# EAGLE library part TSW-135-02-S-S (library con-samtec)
THROUGH-HOLE .025" SQ POST HEADER Source: Samtec TSW.pdf
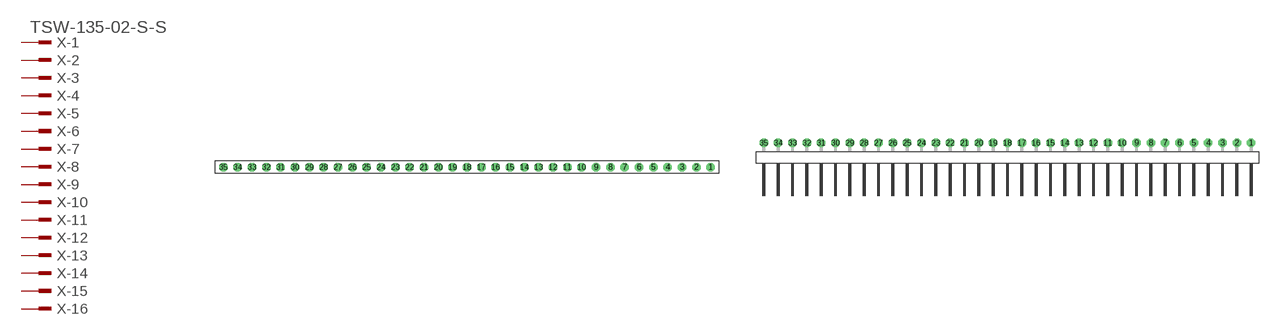
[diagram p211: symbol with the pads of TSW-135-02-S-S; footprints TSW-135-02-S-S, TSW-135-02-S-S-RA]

Designator prefix X; gates -1=MPINV -2=MPIN -3=MPIN -4=MPIN -5=MPIN -6=MPIN -7=MPIN -8=MPIN -9=MPIN -10=MPIN -11=MPIN -12=MPIN -13=MPIN -14=MPIN -15=MPIN -16=MPIN -17=MPIN -18=MPIN -19=MPIN -20=MPIN -21=MPIN -22=MPIN -23=MPIN -24=MPIN -25=MPIN -26=MPIN -27=MPIN -28=MPIN -29=MPIN -30=MPIN -31=MPIN -32=MPIN -33=MPIN -34=MPIN -35=MPIN

## TSW-135-02-S-S (OC_FARNELL: unknown; OC_NEWARK: unknown)  [TSW-135-02-S-S]
1  -1:1  pas
2  -2:1  pas
3  -3:1  pas
4  -4:1  pas
5  -5:1  pas
6  -6:1  pas
7  -7:1  pas
8  -8:1  pas
9  -9:1  pas
10  -10:1  pas
11  -11:1  pas
12  -12:1  pas
13  -13:1  pas
14  -14:1  pas
15  -15:1  pas
16  -16:1  pas
17  -17:1  pas
18  -18:1  pas
19  -19:1  pas
20  -20:1  pas
21  -21:1  pas
22  -22:1  pas
23  -23:1  pas
24  -24:1  pas
25  -25:1  pas
26  -26:1  pas
27  -27:1  pas
28  -28:1  pas
29  -29:1  pas
30  -30:1  pas
31  -31:1  pas
32  -32:1  pas
33  -33:1  pas
34  -34:1  pas
35  -35:1  pas

## TSW-135-02-S-S-RA (OC_FARNELL: unknown; OC_NEWARK: unknown)  [TSW-135-02-S-S-RA]
Pads as for TSW-135-02-S-S

## Footprint TSW-135-02-S-S (pad centres in mm)
THROUGH-HOLE .025" SQ POST HEADER Source: Samtec TSW.pdf
drill 1 pad 1.5 octagon: 1 43.18,0; 2 40.64,0; 3 38.1,0; 4 35.56,0; 5 33.02,0; 6 30.48,0; 7 27.94,0; 8 25.4,0; 9 22.86,0; 10 20.32,0; 11 17.78,0; 12 15.24,0; 13 12.7,0; 14 10.16,0; 15 7.62,0; 16 5.08,0; 17 2.54,0; 18 0,0; 19 -2.54,0; 20 -5.08,0; 21 -7.62,0; 22 -10.16,0; 23 -12.7,0; 24 -15.24,0; 25 -17.78,0; 26 -20.32,0; 27 -22.86,0; 28 -25.4,0; 29 -27.94,0; 30 -30.48,0; 31 -33.02,0; 32 -35.56,0; 33 -38.1,0; 34 -40.64,0; 35 -43.18,0

## Footprint TSW-135-02-S-S-RA (pad centres in mm)
THROUGH-HOLE .025" SQ POST HEADER Source: Samtec TSW.pdf
drill 1 pad 1.5 octagon: 1 43.18,1.524; 2 40.64,1.524; 3 38.1,1.524; 4 35.56,1.524; 5 33.02,1.524; 6 30.48,1.524; 7 27.94,1.524; 8 25.4,1.524; 9 22.86,1.524; 10 20.32,1.524; 11 17.78,1.524; 12 15.24,1.524; 13 12.7,1.524; 14 10.16,1.524; 15 7.62,1.524; 16 5.08,1.524; 17 2.54,1.524; 18 0,1.524; 19 -2.54,1.524; 20 -5.08,1.524; 21 -7.62,1.524; 22 -10.16,1.524; 23 -12.7,1.524; 24 -15.24,1.524; 25 -17.78,1.524; 26 -20.32,1.524; 27 -22.86,1.524; 28 -25.4,1.524; 29 -27.94,1.524; 30 -30.48,1.524; 31 -33.02,1.524; 32 -35.56,1.524; 33 -38.1,1.524; 34 -40.64,1.524; 35 -43.18,1.524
